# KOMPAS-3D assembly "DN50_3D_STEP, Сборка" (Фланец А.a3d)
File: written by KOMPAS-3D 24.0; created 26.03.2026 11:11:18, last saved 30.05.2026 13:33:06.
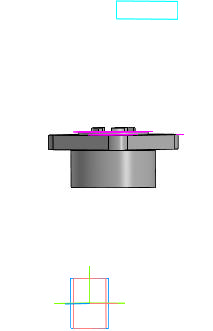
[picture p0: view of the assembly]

Document properties: Автор: R2D2; Полное имя файла: E:\Работа\Зайцев\GVWR2121M-2W-F-ОСТ Задвижка клиновая 30с964нж DN.ru Ду50-300 Ру25\исходные материалы\DN150\Фланец А.a3d

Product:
- Body: Тело 2  | qty 1
    Масса: 2.709631
- Part/product: DN50_3D_STEP  | designation Сборка
    Масса: 2.725126

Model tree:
1. Перпендикулярная плоскость:2
     Координата Z = -90
2. Операция без истории:2
3. Эскиз:1  (with: Грань.Операция без истории:2, Ребро.Операция без истории:2)
4. Элемент выдавливания:1  (with: Грань.Операция без истории:2)
     Расстояние 2 = 14.5
5. Массив по концентрической сетке:1  (with: Элемент выдавливания:1, Грань.Операция без истории:2)  (4 pattern instances)
     Шаг 2 = 360
6. Скругление:1
     Радиус = 13.5
7. Эскиз:2  (with: Грань.Операция без истории:2, Ребро.Операция без истории:2)
8. Элемент выдавливания:2
     Расстояние 2 = 20
9. Эскиз:3  (with: Грань.Операция без истории:2, Ребро.Операция без истории:2)
10. Элемент выдавливания:3  (with: Грань.Операция без истории:2)
     Расстояние 2 = 3
11. Эскиз:4  (with: Грань.Операция без истории:2, Ребро.Операция без истории:2)
12. Элемент выдавливания:4
     Расстояние 1 = 3
13. Эскиз:5  (with: Грань.Операция без истории:2, Ребро.Операция без истории:2)
14. Элемент выдавливания:5
     Расстояние 1 = 1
